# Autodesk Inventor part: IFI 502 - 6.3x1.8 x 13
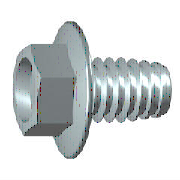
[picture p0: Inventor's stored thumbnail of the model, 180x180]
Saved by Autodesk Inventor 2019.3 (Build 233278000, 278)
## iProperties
Created: 2018-01
Part Number: IFI 502 - 6.3x1.8 x 13
Material: Ocel, měkká
Description: Šroub do plechu s vroubkovanou šestihrannou hlavou s nákružkem - Typ B - Metrický
Document SubType Name: Modeling
Standard: IFI 502
Designer: B-hon
Standards Organization: ANSI
Language: cs-CZ
Size Designation: 6.3x1.8 x 13
Categories: <MemberInstance><Categories><Category DisplayName="Spojovací materiál" InternalName="e4da775c-781d-43d5-af7c-5136215cf5a6" Mnemonic="FSTN"><Category DisplayName
Density: 7.85 g/cm^3
Appearance: Pololeštěná
IsCustomPart: 0
Author: B-hon
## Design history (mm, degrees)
sketch "Náčrt1"
  geometry: L1 (-1.94, 5.742)-(-2.948, 2.972); L2 (-2.948, 2.972)-(-2.948, 0); L3 (-2.948, 0)-(13, 0); L4 (13, 0)-(13, 3.15); L5 (13, 3.15)-(0, 3.15); L6 (0, 3.15)-(0, 5.4); L7 (-6.138, 0)-(16.19, 0) reference; L8 (0, -1.311)-(0, 7.867) reference; A1 r 1 centre (-1, 5.4) between (0, 5.4) and (-1.94, 5.742)
  constraints: 12 end point, 3 perpendicular, 2 collinear, 2 point on circle, 2 tangent, 1 centre point, 1 point on line, 1 vertical
  dimensions: "d0" = 1 radius of A1 (= PHH); "d1" = 2.948 distance between parallel lines of L2 L6 (= 0.44 x KOH); "d2" = 6.3 diameter of L5 L3 (= NND); "d3" = 13 distance between parallel lines of L4 L6 (= NLG); "d4" = 20 deg angle of L6 L1 (= KEWI); "d5" = 12.8 dimension on A1 L3 (= LADI)
revolve "Těleso" sketch "Náčrt1" stored, may be unused: angle "d77" = 90 deg
sketch "Náčrt2"
  geometry: L1 (0, 4.619)-(4, 2.309); L2 (4, 2.309)-(4, -2.309); L3 (4, -2.309)-(0, -4.619); L4 (0, -4.619)-(-4, -2.309); L5 (-4, -2.309)-(-4, 2.309); L6 (-4, 2.309)-(0, 4.619); C1 r 5.4 at (0, 0) reference; 1 further point
  constraints: 12 end point, 1 coincident, 1 vertical, 11 other
  dimensions: "d11" = 8 distance between parallel lines of L2 L5 (= SW)
extrude "Hlava" join sketch "Náčrt2" distance "d12" = 6.7 (= KOH); taper "d13" = 0 deg
node "IDS_WORKPLANE{1}"
sketch "Náčrt3"
  geometry: C1 r 3.2 at (0, 0); 1 further point
  constraints: 1 centre point, 1 coincident
  dimensions: "d15" = 6.4 diameter of C1 (= KOD2)
extrude "Zářez" cut sketch "Náčrt3" distance "d16" = 2.01 (= KOH2); taper "d17" = 0 deg
sketch "Náčrt4"
  geometry: L1 (-6.7, 4)-(-6.7, 4.619); L2 (-6.7, 4.619)-(-6.343, 4.619); L3 (-6.343, 4.619)-(-6.7, 4); L4 (-2.349, 4.619)-(-6.7, 4.619) reference; L5 (-6.7, 4.619)-(-6.7, 2.309) reference; L6 (-7.57, 0)-(-1.478, 0) reference
  constraints: 6 end point, 2 collinear, 1 perpendicular, 1 vertical
  dimensions: "d18" = 30 deg angle of L3 L1 (= ANG1); "d21" = 8 diameter of L1.start L6 (= SW)
revolve "Zkosení1" sketch "Náčrt4" stored, may be unused: angle "d92" = 90 deg
workplane "Work Plane3"
body "Solid1"
feature "Závit" dims "d6" = 13 (= GEL), "d7" = 0
fillet "Zaoblení1" dims "d8" = 0.3 (= RR)
chamfer "Zkosení2" distance "d19" = 0.875 (= -0.5 x GD2 + 0.5 x NND); stored, may be unused: second distance "d20" = 3.6 (= SPTZ), angle "d96" = 45 deg
other parameters: "NLG" = 13 [user parameter; used in 1 equation term], "NND" = 6.3 [user parameter; used in 2 equation terms], "KOH" = 6.7 [user parameter; used in 3 equation terms], "GEL" = 13 [user parameter; used in 1 equation term], "LADI" = 12.8 [user parameter; used in 1 equation term], "SW" = 8 [user parameter; used in 4 equation terms], "PHH" = 1 [user parameter; used in 1 equation term], "GD2" = 4.55 [user parameter; used in 1 equation term], "ANG1" = 30 deg [user parameter; used in 1 equation term], "KEWI" = 20 deg [user parameter; used in 1 equation term], "SPTZ" = 3.6 [user parameter; used in 1 equation term], "RR" = 0.3 [user parameter; used in 1 equation term], "KOD2" = 6.4 (= 0.8 x SW) [user parameter; used in 1 equation term], "KOH2" = 2.01 (= 0.3 x KOH) [user parameter; used in 1 equation term], "d10" = 0, "d14" = 0, "d97" = 0, "d98" = 0, "THREADDIA" = 6.3 [user parameter], "TOA" = 30 deg [user parameter], "TPU" = 5.55556 (computed from PTC) [user parameter], "PTC" = 1.8 [user parameter; used in 1 equation term], "E0" = 9.24 (= 1.155 x SW) [user parameter], "GD1" = 4.88 [user parameter]
